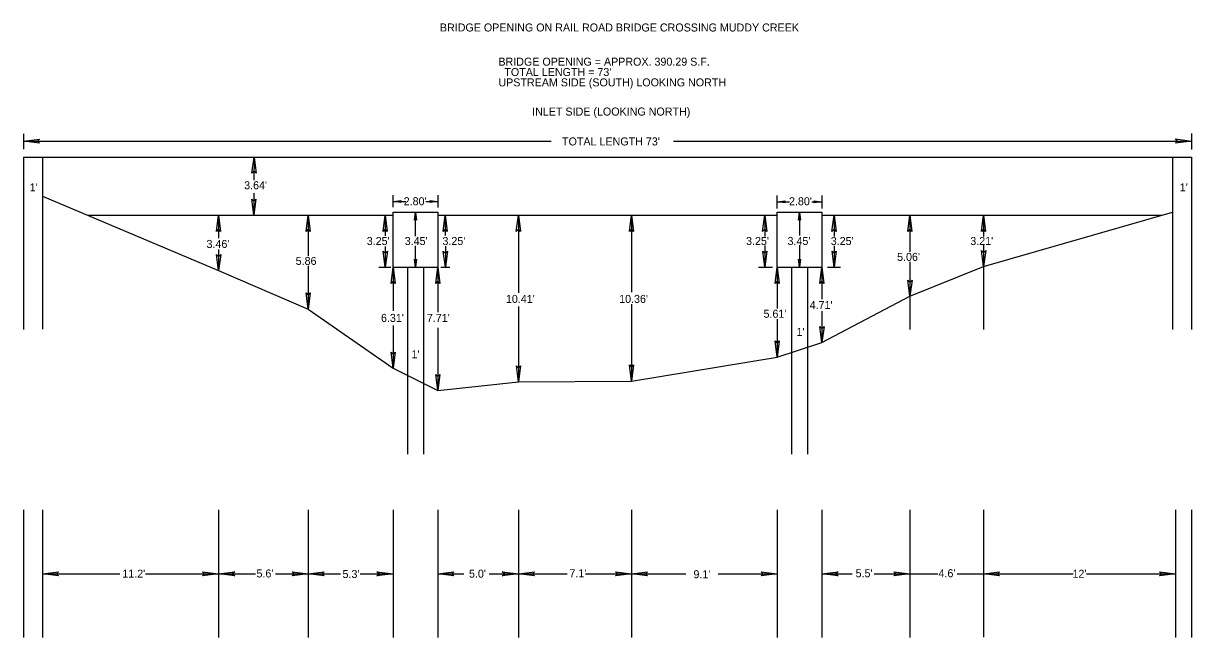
# Model space of a CAD drawing. Extents: x -200 to 949611, y -218 to 425120.
# Drawn here: x 947795 to 948525, y 424137 to 424521 of the extents above; entities that cross this region are included whole.
import ezdxf

# ---------------------------------------------------------------- set-up
doc = ezdxf.new("R2010")
doc.units = 0
doc.layers.add('SURVEY - PROFILE - Drainage - Bridge Hydraulic Data with Text', color=7, linetype='Continuous')

msp = doc.modelspace()

# ---------------------------------------------------------------- linework, layer by layer
at = {"layer": 'SURVEY - PROFILE - Drainage - Bridge Hydraulic Data with Text'}
for p, q in [((947795.42, 424451.71), (947795.42, 424442.02)), ((948525.42, 424451.86), (948525.42, 424441.85)), ((947795.42, 424447.18), (948125.13, 424447.18)), ((948201.61, 424447.18), (948525.42, 424447.18)), ((947795.42, 424437.18), (947807.42, 424437.18)), ((947795.42, 424437.18), (947795.42, 424329.36)), ((947807.42, 424437.18), (948513.42, 424437.18)), ((947807.42, 424437.18), (947807.42, 424329.61)), ((947939.58, 424437.18), (947939.53, 424422.76)), ((948513.42, 424437.18), (948513.42, 424329.36)), ((948513.42, 424437.18), (948525.42, 424437.18)), ((948525.42, 424437.18), (948525.42, 424329.36)), ((947807.42, 424412.68), (947917.42, 424366.18)), ((947939.51, 424414.65), (947939.46, 424400.78)), ((948026.42, 424405.81), (948026.42, 424413.45)), ((948026.42, 424409.34), (948034.32, 424409.34)), ((948046.93, 424409.34), (948054.42, 424409.34)), ((948054.42, 424413.45), (948054.42, 424405.65)), ((948266.42, 424405.07), (948266.42, 424413.24)), ((948266.42, 424409.23), (948274.17, 424409.23)), ((948288.01, 424409.23), (948294.45, 424409.23)), ((948294.42, 424413.22), (948294.42, 424405.07)), ((947835.58, 424400.78), (948026.42, 424400.78)), ((947917.42, 424400.78), (947917.42, 424386.51)), ((947973.42, 424400.78), (947973.42, 424375.49)), ((948021.59, 424400.78), (948021.6, 424388.02)), ((948026.42, 424402.78), (948054.42, 424402.78)), ((948026.42, 424368.28), (948026.42, 424402.78)), ((948040.42, 424387.72), (948040.42, 424402.78)), ((948054.42, 424402.78), (948054.42, 424368.28)), ((948054.42, 424400.78), (948266.42, 424400.78)), ((948059.09, 424400.78), (948059.09, 424388.09)), ((948104.72, 424400.78), (948104.72, 424352.28)), ((948175.42, 424400.78), (948175.42, 424352.8)), ((948258.65, 424400.78), (948258.65, 424387.54)), ((948266.42, 424402.78), (948294.42, 424402.78)), ((948266.42, 424368.28), (948266.42, 424402.78)), ((948280.42, 424402.78), (948280.42, 424388.24)), ((948294.42, 424402.78), (948294.42, 424368.28)), ((948294.42, 424400.78), (948506.5, 424400.78)), ((948302, 424400.78), (948302, 424387.5)), ((948349.42, 424400.78), (948349.42, 424377.91)), ((948395.42, 424368.68), (948513.42, 424402.78)), ((948395.42, 424400.78), (948395.42, 424387.53)), ((947917.42, 424379.45), (947917.42, 424366.18)), ((948021.6, 424381.35), (948021.6, 424368.28)), ((948040.42, 424368.28), (948040.42, 424381.79)), ((948059.1, 424381.38), (948059.1, 424368.28)), ((948258.65, 424381.8), (948258.65, 424368.28)), ((948280.42, 424382.03), (948280.42, 424368.28)), ((948302, 424381.69), (948302, 424368.28)), ((948395.42, 424382.04), (948395.42, 424329.36)), ((948349.42, 424371.78), (948349.42, 424329.36)), ((947917.42, 424366.18), (947973.42, 424342.18)), ((947973.42, 424369.2), (947973.42, 424342.18)), ((948017.62, 424368.28), (948025.04, 424368.28)), ((948026.42, 424368.28), (948026.42, 424341.09)), ((948026.42, 424368.28), (948054.43, 424368.28)), ((948035.42, 424368.28), (948035.42, 424251.57)), ((948045.42, 424368.28), (948045.42, 424251.57)), ((948054.42, 424368.28), (948054.42, 424340.31)), ((948056.3, 424368.28), (948061.91, 424368.28)), ((948254.8, 424368.28), (948263.57, 424368.28)), ((948266.42, 424368.28), (948266.42, 424342.52)), ((948266.43, 424368.28), (948294.41, 424368.28)), ((948275.42, 424368.28), (948275.42, 424251.57)), ((948285.42, 424368.28), (948285.42, 424251.57)), ((948294.42, 424368.28), (948294.42, 424348.38)), ((948297.84, 424368.28), (948306.11, 424368.28)), ((948349.42, 424350.18), (948395.42, 424368.68)), ((948294.42, 424321.18), (948349.42, 424350.18)), ((947973.42, 424342.18), (948026.42, 424305.18)), ((948104.72, 424343.84), (948104.72, 424296.68)), ((948175.42, 424345.26), (948175.42, 424297.18)), ((948266.42, 424335.78), (948266.42, 424312.18)), ((948294.42, 424340.84), (948294.42, 424321.18)), ((948026.42, 424331.95), (948026.42, 424305.18)), ((948054.42, 424330.49), (948054.42, 424291.18)), ((948266.42, 424312.18), (948294.42, 424321.18)), ((948175.42, 424297.18), (948266.42, 424312.18)), ((948026.42, 424305.18), (948054.42, 424291.18)), ((948054.42, 424291.18), (948104.72, 424296.68)), ((948104.72, 424296.68), (948175.42, 424297.18)), ((947795.42, 424216.69), (947795.42, 424136.84)), ((947807.42, 424216.69), (947807.42, 424136.84)), ((947917.42, 424216.69), (947917.42, 424136.84)), ((947973.42, 424216.69), (947973.42, 424136.84)), ((948026.42, 424216.69), (948026.42, 424136.84)), ((948054.42, 424216.69), (948054.42, 424136.84)), ((948104.72, 424216.69), (948104.72, 424136.84)), ((948175.42, 424216.69), (948175.42, 424136.84)), ((948266.42, 424216.69), (948266.42, 424136.84)), ((948294.42, 424216.69), (948294.42, 424136.84)), ((948349.42, 424216.69), (948349.42, 424136.84)), ((948395.42, 424216.69), (948395.42, 424137.16)), ((948515.42, 424216.69), (948515.42, 424136.84)), ((948525.42, 424216.69), (948525.42, 424136.84)), ((947807.42, 424176.69), (947855.7, 424176.69)), ((947871.68, 424176.69), (947917.42, 424176.69)), ((947917.42, 424176.69), (947940.47, 424176.69)), ((947953.06, 424176.69), (947973.42, 424176.69)), ((947973.42, 424176.69), (947993.55, 424176.69)), ((948005.81, 424176.69), (948026.42, 424176.69)), ((948054.42, 424176.69), (948070.59, 424176.69)), ((948086.52, 424176.69), (948104.72, 424176.69)), ((948104.72, 424176.69), (948135.21, 424176.69)), ((948146.76, 424176.69), (948175.43, 424176.69)), ((948175.43, 424176.69), (948209.34, 424176.69)), ((948229.62, 424176.69), (948266.42, 424176.69)), ((948294.42, 424176.69), (948313.31, 424176.69)), ((948327, 424176.69), (948349.42, 424176.69)), ((948349.42, 424176.69), (948366.79, 424176.69)), ((948378.93, 424176.69), (948395.42, 424176.69)), ((948395.42, 424176.69), (948451.34, 424176.69)), ((948459.7, 424176.69), (948515.42, 424176.69))]:
    msp.add_line(p, q, dxfattribs=at)
for points in [[(947795.42, 424447.18), (947805.47, 424448.43), (947804.17, 424447.18), (947805.47, 424445.88)], [(948525.42, 424447.18), (948515.37, 424445.93), (948516.67, 424447.18), (948515.37, 424448.48)], [(947939.58, 424437.18), (947940.83, 424427.13), (947939.58, 424428.43), (947938.28, 424427.13)], [(947939.46, 424400.78), (947938.21, 424410.83), (947939.46, 424409.53), (947940.76, 424410.83)], [(948026.42, 424409.34), (948031.47, 424409.99), (948030.82, 424409.34), (948031.47, 424408.69)], [(948054.42, 424409.34), (948049.37, 424408.69), (948050.02, 424409.34), (948049.37, 424409.99)], [(948266.42, 424409.23), (948271.47, 424409.88), (948270.82, 424409.23), (948271.47, 424408.58)], [(948294.42, 424409.23), (948289.37, 424408.58), (948290.02, 424409.23), (948289.37, 424409.88)], [(947917.42, 424400.78), (947918.68, 424390.73), (947917.43, 424392.03), (947916.13, 424390.73)], [(947973.42, 424400.78), (947974.64, 424390.72), (947973.4, 424392.03), (947972.09, 424390.73)], [(948021.59, 424400.78), (948022.81, 424390.72), (948021.57, 424392.03), (948020.26, 424390.73)], [(948040.42, 424402.78), (948041.07, 424397.73), (948040.42, 424398.38), (948039.77, 424397.73)], [(948059.09, 424400.78), (948060.31, 424390.72), (948059.06, 424392.03), (948057.76, 424390.73)], [(948104.72, 424400.78), (948105.98, 424390.73), (948104.73, 424392.03), (948103.43, 424390.73)], [(948175.42, 424400.78), (948176.68, 424390.73), (948175.43, 424392.03), (948174.13, 424390.73)], [(948258.65, 424400.78), (948259.91, 424390.73), (948258.66, 424392.03), (948257.36, 424390.73)], [(948280.42, 424402.78), (948281.07, 424397.73), (948280.42, 424398.38), (948279.77, 424397.73)], [(948302, 424400.78), (948303.25, 424390.73), (948302, 424392.03), (948300.7, 424390.73)], [(948349.42, 424400.78), (948350.68, 424390.73), (948349.43, 424392.03), (948348.13, 424390.73)], [(948395.42, 424400.78), (948396.68, 424390.73), (948395.43, 424392.03), (948394.13, 424390.73)], [(948021.6, 424368.28), (948020.34, 424378.33), (948021.59, 424377.03), (948022.89, 424378.33)], [(948059.1, 424368.28), (948057.84, 424378.33), (948059.09, 424377.03), (948060.39, 424378.33)], [(948258.65, 424368.28), (948257.39, 424378.33), (948258.64, 424377.03), (948259.94, 424378.33)], [(948302, 424368.28), (948300.75, 424378.33), (948302, 424377.03), (948303.3, 424378.33)], [(948395.42, 424368.68), (948394.18, 424378.73), (948395.43, 424377.43), (948396.73, 424378.73)], [(947917.42, 424366.18), (947916.17, 424376.23), (947917.42, 424374.93), (947918.72, 424376.23)], [(948040.42, 424368.28), (948039.77, 424373.33), (948040.42, 424372.68), (948041.07, 424373.33)], [(948280.42, 424368.28), (948279.77, 424373.33), (948280.42, 424372.68), (948281.07, 424373.33)], [(948026.42, 424368.28), (948027.7, 424358.23), (948026.44, 424359.53), (948025.15, 424358.22)], [(948054.42, 424368.28), (948055.68, 424358.23), (948054.43, 424359.53), (948053.13, 424358.23)], [(948266.42, 424368.28), (948267.68, 424358.23), (948266.43, 424359.53), (948265.13, 424358.23)], [(948294.42, 424368.28), (948295.68, 424358.23), (948294.43, 424359.53), (948293.13, 424358.23)], [(948349.42, 424350.18), (948348.18, 424360.23), (948349.43, 424358.93), (948350.73, 424360.23)], [(947973.42, 424342.18), (947972.16, 424352.23), (947973.41, 424350.93), (947974.71, 424352.23)], [(948294.42, 424321.18), (948293.18, 424331.23), (948294.43, 424329.93), (948295.73, 424331.23)], [(948266.42, 424312.18), (948265.18, 424322.23), (948266.43, 424320.93), (948267.73, 424322.23)], [(948026.42, 424305.18), (948025.18, 424315.23), (948026.43, 424313.93), (948027.73, 424315.23)], [(948104.72, 424296.68), (948103.48, 424306.73), (948104.73, 424305.43), (948106.03, 424306.73)], [(948175.42, 424297.18), (948174.18, 424307.23), (948175.43, 424305.93), (948176.73, 424307.23)], [(948054.42, 424291.18), (948053.18, 424301.23), (948054.43, 424299.93), (948055.73, 424301.23)], [(947807.42, 424176.69), (947817.47, 424177.94), (947816.17, 424176.69), (947817.47, 424175.39)], [(947917.42, 424176.69), (947907.37, 424175.44), (947908.67, 424176.69), (947907.37, 424177.99)], [(947917.42, 424176.69), (947927.47, 424177.94), (947926.17, 424176.69), (947927.47, 424175.39)], [(947973.42, 424176.69), (947963.37, 424175.44), (947964.67, 424176.69), (947963.37, 424177.99)], [(947973.42, 424176.69), (947983.47, 424177.94), (947982.17, 424176.69), (947983.47, 424175.39)], [(948026.42, 424176.69), (948016.37, 424175.44), (948017.67, 424176.69), (948016.37, 424177.99)], [(948054.42, 424176.69), (948064.47, 424177.94), (948063.17, 424176.69), (948064.47, 424175.39)], [(948104.72, 424176.69), (948094.67, 424175.44), (948095.97, 424176.69), (948094.67, 424177.99)], [(948104.72, 424176.69), (948114.77, 424177.94), (948113.47, 424176.69), (948114.77, 424175.39)], [(948175.42, 424176.69), (948165.37, 424175.44), (948166.67, 424176.69), (948165.37, 424177.99)], [(948175.42, 424176.69), (948185.47, 424177.94), (948184.17, 424176.69), (948185.47, 424175.39)], [(948266.42, 424176.69), (948256.37, 424175.44), (948257.67, 424176.69), (948256.37, 424177.99)], [(948294.42, 424176.69), (948304.47, 424177.94), (948303.17, 424176.69), (948304.47, 424175.39)], [(948349.42, 424176.69), (948339.37, 424175.44), (948340.67, 424176.69), (948339.37, 424177.99)], [(948395.42, 424176.69), (948405.47, 424177.94), (948404.17, 424176.69), (948405.47, 424175.39)], [(948515.42, 424176.69), (948505.37, 424175.44), (948506.67, 424176.69), (948505.37, 424177.99)]]:
    msp.add_lwpolyline(points, close=True, dxfattribs=at)
for points in [[(947795.42, 424447.18), (947805.47, 424448.43), (947804.17, 424447.18), (947805.47, 424445.88), (947795.42, 424447.18)], [(948525.42, 424447.18), (948515.37, 424445.93), (948516.67, 424447.18), (948515.37, 424448.48), (948525.42, 424447.18)], [(947939.58, 424437.18), (947940.83, 424427.13), (947939.58, 424428.43), (947938.28, 424427.13), (947939.58, 424437.18)], [(947939.46, 424400.78), (947938.21, 424410.83), (947939.46, 424409.53), (947940.76, 424410.83), (947939.46, 424400.78)], [(948026.42, 424409.34), (948031.47, 424409.99), (948030.82, 424409.34), (948031.47, 424408.69), (948026.42, 424409.34)], [(948054.42, 424409.34), (948049.37, 424408.69), (948050.02, 424409.34), (948049.37, 424409.99), (948054.42, 424409.34)], [(948266.42, 424409.23), (948271.47, 424409.88), (948270.82, 424409.23), (948271.47, 424408.58), (948266.42, 424409.23)], [(948294.42, 424409.23), (948289.37, 424408.58), (948290.02, 424409.23), (948289.37, 424409.88), (948294.42, 424409.23)], [(947917.42, 424400.78), (947918.68, 424390.73), (947917.43, 424392.03), (947916.13, 424390.73), (947917.42, 424400.78)], [(947973.42, 424400.78), (947974.64, 424390.72), (947973.4, 424392.03), (947972.09, 424390.73), (947973.42, 424400.78)], [(948021.59, 424400.78), (948022.81, 424390.72), (948021.57, 424392.03), (948020.26, 424390.73), (948021.59, 424400.78)], [(948040.42, 424402.78), (948041.07, 424397.73), (948040.42, 424398.38), (948039.77, 424397.73), (948040.42, 424402.78)], [(948059.09, 424400.78), (948060.31, 424390.72), (948059.06, 424392.03), (948057.76, 424390.73), (948059.09, 424400.78)], [(948104.72, 424400.78), (948105.98, 424390.73), (948104.73, 424392.03), (948103.43, 424390.73), (948104.72, 424400.78)], [(948175.42, 424400.78), (948176.68, 424390.73), (948175.43, 424392.03), (948174.13, 424390.73), (948175.42, 424400.78)], [(948258.65, 424400.78), (948259.91, 424390.73), (948258.66, 424392.03), (948257.36, 424390.73), (948258.65, 424400.78)], [(948280.42, 424402.78), (948281.07, 424397.73), (948280.42, 424398.38), (948279.77, 424397.73), (948280.42, 424402.78)], [(948302, 424400.78), (948303.25, 424390.73), (948302, 424392.03), (948300.7, 424390.73), (948302, 424400.78)], [(948349.42, 424400.78), (948350.68, 424390.73), (948349.43, 424392.03), (948348.13, 424390.73), (948349.42, 424400.78)], [(948395.42, 424400.78), (948396.68, 424390.73), (948395.43, 424392.03), (948394.13, 424390.73), (948395.42, 424400.78)], [(948021.6, 424368.28), (948020.34, 424378.33), (948021.59, 424377.03), (948022.89, 424378.33), (948021.6, 424368.28)], [(948059.1, 424368.28), (948057.84, 424378.33), (948059.09, 424377.03), (948060.39, 424378.33), (948059.1, 424368.28)], [(948258.65, 424368.28), (948257.39, 424378.33), (948258.64, 424377.03), (948259.94, 424378.33), (948258.65, 424368.28)], [(948302, 424368.28), (948300.75, 424378.33), (948302, 424377.03), (948303.3, 424378.33), (948302, 424368.28)], [(948395.42, 424368.68), (948394.18, 424378.73), (948395.43, 424377.43), (948396.73, 424378.73), (948395.42, 424368.68)], [(947917.42, 424366.18), (947916.17, 424376.23), (947917.42, 424374.93), (947918.72, 424376.23), (947917.42, 424366.18)], [(948040.42, 424368.28), (948039.77, 424373.33), (948040.42, 424372.68), (948041.07, 424373.33), (948040.42, 424368.28)], [(948280.42, 424368.28), (948279.77, 424373.33), (948280.42, 424372.68), (948281.07, 424373.33), (948280.42, 424368.28)], [(948026.42, 424368.28), (948027.7, 424358.23), (948026.44, 424359.53), (948025.15, 424358.22), (948026.42, 424368.28)], [(948054.42, 424368.28), (948055.68, 424358.23), (948054.43, 424359.53), (948053.13, 424358.23), (948054.42, 424368.28)], [(948266.42, 424368.28), (948267.68, 424358.23), (948266.43, 424359.53), (948265.13, 424358.23), (948266.42, 424368.28)], [(948294.42, 424368.28), (948295.68, 424358.23), (948294.43, 424359.53), (948293.13, 424358.23), (948294.42, 424368.28)], [(948349.42, 424350.18), (948348.18, 424360.23), (948349.43, 424358.93), (948350.73, 424360.23), (948349.42, 424350.18)], [(947973.42, 424342.18), (947972.16, 424352.23), (947973.41, 424350.93), (947974.71, 424352.23), (947973.42, 424342.18)], [(948294.42, 424321.18), (948293.18, 424331.23), (948294.43, 424329.93), (948295.73, 424331.23), (948294.42, 424321.18)], [(948266.42, 424312.18), (948265.18, 424322.23), (948266.43, 424320.93), (948267.73, 424322.23), (948266.42, 424312.18)], [(948026.42, 424305.18), (948025.18, 424315.23), (948026.43, 424313.93), (948027.73, 424315.23), (948026.42, 424305.18)], [(948104.72, 424296.68), (948103.48, 424306.73), (948104.73, 424305.43), (948106.03, 424306.73), (948104.72, 424296.68)], [(948175.42, 424297.18), (948174.18, 424307.23), (948175.43, 424305.93), (948176.73, 424307.23), (948175.42, 424297.18)], [(948054.42, 424291.18), (948053.18, 424301.23), (948054.43, 424299.93), (948055.73, 424301.23), (948054.42, 424291.18)], [(947807.42, 424176.69), (947817.47, 424177.94), (947816.17, 424176.69), (947817.47, 424175.39), (947807.42, 424176.69)], [(947917.42, 424176.69), (947907.37, 424175.44), (947908.67, 424176.69), (947907.37, 424177.99), (947917.42, 424176.69)], [(947917.42, 424176.69), (947927.47, 424177.94), (947926.17, 424176.69), (947927.47, 424175.39), (947917.42, 424176.69)], [(947973.42, 424176.69), (947963.37, 424175.44), (947964.67, 424176.69), (947963.37, 424177.99), (947973.42, 424176.69)], [(947973.42, 424176.69), (947983.47, 424177.94), (947982.17, 424176.69), (947983.47, 424175.39), (947973.42, 424176.69)], [(948026.42, 424176.69), (948016.37, 424175.44), (948017.67, 424176.69), (948016.37, 424177.99), (948026.42, 424176.69)], [(948054.42, 424176.69), (948064.47, 424177.94), (948063.17, 424176.69), (948064.47, 424175.39), (948054.42, 424176.69)], [(948104.72, 424176.69), (948094.67, 424175.44), (948095.97, 424176.69), (948094.67, 424177.99), (948104.72, 424176.69)], [(948104.72, 424176.69), (948114.77, 424177.94), (948113.47, 424176.69), (948114.77, 424175.39), (948104.72, 424176.69)], [(948175.42, 424176.69), (948165.37, 424175.44), (948166.67, 424176.69), (948165.37, 424177.99), (948175.42, 424176.69)], [(948175.42, 424176.69), (948185.47, 424177.94), (948184.17, 424176.69), (948185.47, 424175.39), (948175.42, 424176.69)], [(948266.42, 424176.69), (948256.37, 424175.44), (948257.67, 424176.69), (948256.37, 424177.99), (948266.42, 424176.69)], [(948294.42, 424176.69), (948304.47, 424177.94), (948303.17, 424176.69), (948304.47, 424175.39), (948294.42, 424176.69)], [(948349.42, 424176.69), (948339.37, 424175.44), (948340.67, 424176.69), (948339.37, 424177.99), (948349.42, 424176.69)], [(948395.42, 424176.69), (948405.47, 424177.94), (948404.17, 424176.69), (948405.47, 424175.39), (948395.42, 424176.69)], [(948515.42, 424176.69), (948505.37, 424175.44), (948506.67, 424176.69), (948505.37, 424177.99), (948515.42, 424176.69)]]:
    msp.add_lwpolyline(points, dxfattribs=at)

# ---------------------------------------------------------------- texts
for s, p in [('BRIDGE OPENING ON RAIL ROAD BRIDGE CROSSING MUDDY CREEK', (948055.69, 424515.64)), ('BRIDGE OPENING = APPROX. 390.29 S.F.', (948092.26, 424494.27)), ("  TOTAL LENGTH = 73' ", (948092.26, 424487.8)), ('UPSTREAM SIDE (SOUTH) LOOKING NORTH', (948092.26, 424481.33)), ('INLET SIDE (LOOKING NORTH)', (948113.35, 424463.1)), ("TOTAL LENGTH 73'", (948132.02, 424444.43)), ("3.64'", (947933.38, 424417.04)), ("1'", (947799.39, 424415.74)), ("1'", (948518.01, 424415.74)), ("2.80'", (948033.08, 424407.06)), ("2.80'", (948273.85, 424407.06)), ("3.25'", (948009.98, 424382.21)), ("3.45'", (948033.73, 424382.21)), ("3.25'", (948057.3, 424382.21)), ("3.25'", (948247.01, 424382.21)), ("3.45'", (948272.93, 424382.21)), ("3.25'", (948299.93, 424382.21)), ("3.21'", (948387.12, 424382.22)), ("3.46'", (947909.87, 424380.37)), ('5.86', (947965.59, 424369.77)), ("5.06'", (948341.39, 424372.27)), ("10.41'", (948096.95, 424346.02)), ("10.36'", (948167.71, 424346.02)), ("5.61'", (948257.91, 424336.74)), ("4.71'", (948286.73, 424342.2)), ("6.31'", (948018.88, 424334.15)), ("7.71'", (948047.56, 424334.15)), ("1'", (948278.52, 424325.4)), ("1'", (948037.95, 424311.48)), ("11.2'", (947857.27, 424174.33)), ("5.6'", (947941.08, 424174.45)), ("5.3'", (947994.83, 424174.09)), ("5.0'", (948073.88, 424174.33)), ("7.1'", (948136.64, 424174.58)), ("9.1'", (948214.13, 424173.97)), ("5.5'", (948315.46, 424174.58)), ("4.6'", (948367.26, 424174.58)), ("12'", (948450.97, 424174.26))]:
    msp.add_text(s, height=5, dxfattribs=at).set_placement(p)

doc.saveas('drawing.dxf')
